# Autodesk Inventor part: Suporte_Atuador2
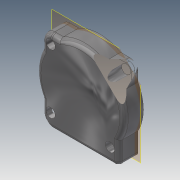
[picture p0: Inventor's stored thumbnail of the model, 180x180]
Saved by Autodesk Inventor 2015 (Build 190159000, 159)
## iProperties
Created: 2015-04
Part Number: Suporte_Atuador2
Material: Steel, Carbon
Document SubType Name: Modeling
Designer: TREINA6
Density: 7.85 g/cm^3
Appearance: Semi-Polished
Author: TREINA6
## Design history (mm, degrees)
workplane "Work Plane1"
sketch "Sketch1"
  geometry: L1 (32.5, -27.5)-(32.5, -18.708) reference; L2 (32.5, 18.708)-(32.5, 27.5) reference; L3 (27.5, 32.5)-(18.708, 32.5) reference; L4 (-18.708, 32.5)-(-27.5, 32.5) reference; L5 (-32.5, 27.5)-(-32.5, 18.708) reference; L6 (-32.5, -18.708)-(-32.5, -27.5) reference; L7 (-27.5, -32.5)-(-18.708, -32.5) reference; L8 (18.708, -32.5)-(27.5, -32.5) reference; L9 (35.5, -19.494)-(35.5, -27.5); L10 (27.5, -35.5)-(19.494, -35.5); L11 (-19.494, -35.5)-(-27.5, -35.5); L12 (-35.5, -27.5)-(-35.5, -19.494); L13 (-35.5, 19.494)-(-35.5, 27.5); L14 (-27.5, 35.5)-(-19.494, 35.5); L15 (19.494, 35.5)-(27.5, 35.5); L16 (35.5, 27.5)-(35.5, 19.494); C1 r 3.324 at (27.5, -27.5) reference; C2 r 3.324 at (-27.5, -27.5) reference; C3 r 3.324 at (-27.5, 27.5) reference; C4 r 3.324 at (27.5, 27.5) reference; C5 r 25 at (0, 0) reference; A1 r 5 centre (27.5, -27.5) between (27.5, -32.5) and (32.5, -27.5) reference; A2 r 37.5 centre (0, 0) between (32.5, -18.708) and (32.5, 18.708) reference; A3 r 5 centre (27.5, 27.5) between (32.5, 27.5) and (27.5, 32.5) reference; A4 r 37.5 centre (0, 0) between (18.708, 32.5) and (-18.708, 32.5) reference; A5 r 5 centre (-27.5, 27.5) between (-27.5, 32.5) and (-32.5, 27.5) reference; A6 r 37.5 centre (0, 0) between (-32.5, 18.708) and (-32.5, -18.708) reference; A7 r 5 centre (-27.5, -27.5) between (-32.5, -27.5) and (-27.5, -32.5) reference; A8 r 37.5 centre (0, 0) between (-18.708, -32.5) and (18.708, -32.5) reference; A9 r 40.5 centre (0, 0) between (35.5, -19.494) and (35.5, 19.494); A10 r 8 centre (27.5, -27.5) between (27.5, -35.5) and (35.5, -27.5); A11 r 40.5 centre (0, 0) between (-19.494, -35.5) and (19.494, -35.5); A12 r 8 centre (-27.5, -27.5) between (-35.5, -27.5) and (-27.5, -35.5); A13 r 40.5 centre (0, 0) between (-35.5, 19.494) and (-35.5, -19.494); A14 r 8 centre (-27.5, 27.5) between (-27.5, 35.5) and (-35.5, 27.5); A15 r 40.5 centre (0, 0) between (19.494, 35.5) and (-19.494, 35.5); A16 r 8 centre (27.5, 27.5) between (35.5, 27.5) and (27.5, 35.5); 1 further point
  constraints: 16 end point, 16 point on circle, 8 centre point, 15 other
  dimensions: "d0" = 3 radial gap between concentric circles of A2 A9
extrude "Extrusion1" new body sketch "Sketch1" distance "d1" = 15; taper "d3" = 0 deg; dims "d2" = 3, "d4" = 0
sketch "Sketch2"
  geometry: L1 (27.5, -32.5)-(18.708, -32.5) reference; L2 (-18.708, -32.5)-(-27.5, -32.5) reference; L3 (-32.5, -27.5)-(-32.5, -18.708) reference; L4 (-32.5, 18.708)-(-32.5, 27.5) reference; L5 (-27.5, 32.5)-(-18.708, 32.5) reference; L6 (18.708, 32.5)-(27.5, 32.5) reference; L7 (32.5, 27.5)-(32.5, 18.708) reference; L8 (32.5, -18.708)-(32.5, -27.5) reference; L9 (35.5, 19.494)-(35.5, 27.5) reference; L10 (27.5, 35.5)-(19.494, 35.5) reference; L11 (-19.494, 35.5)-(-27.5, 35.5) reference; L12 (-35.5, 27.5)-(-35.5, 19.494) reference; L13 (-35.5, -19.494)-(-35.5, -27.5) reference; L14 (-27.5, -35.5)-(-19.494, -35.5) reference; L15 (19.494, -35.5)-(27.5, -35.5) reference; L16 (35.5, -27.5)-(35.5, -19.494) reference; A1 r 37.5 centre (0, 0) between (-18.708, -32.5) and (18.708, -32.5) reference; A2 r 5 centre (-27.5, -27.5) between (-32.5, -27.5) and (-27.5, -32.5) reference; A3 r 37.5 centre (0, 0) between (-32.5, 18.708) and (-32.5, -18.708) reference; A4 r 5 centre (-27.5, 27.5) between (-27.5, 32.5) and (-32.5, 27.5) reference; A5 r 37.5 centre (0, 0) between (18.708, 32.5) and (-18.708, 32.5) reference; A6 r 5 centre (27.5, 27.5) between (32.5, 27.5) and (27.5, 32.5) reference; A7 r 37.5 centre (0, 0) between (32.5, -18.708) and (32.5, 18.708) reference; A8 r 5 centre (27.5, -27.5) between (27.5, -32.5) and (32.5, -27.5) reference; A9 r 40.5 centre (0, 0) between (35.5, -19.494) and (35.5, 19.494) reference; A10 r 8 centre (27.5, 27.5) between (35.5, 27.5) and (27.5, 35.5) reference; A11 r 40.5 centre (0, 0) between (19.494, 35.5) and (-19.494, 35.5) reference; A12 r 8 centre (-27.5, 27.5) between (-27.5, 35.5) and (-35.5, 27.5) reference; A13 r 40.5 centre (0, 0) between (-35.5, 19.494) and (-35.5, -19.494) reference; A14 r 8 centre (-27.5, -27.5) between (-35.5, -27.5) and (-27.5, -35.5) reference; A15 r 40.5 centre (0, 0) between (-19.494, -35.5) and (19.494, -35.5) reference; A16 r 8 centre (27.5, -27.5) between (27.5, -35.5) and (35.5, -27.5) reference; 1 further point
extrude "Extrusion2" join sketch "Sketch2" distance "d5" = 15; taper "d6" = 0 deg
hole "Hole1" diameter "d9" = 8.5; stored, may be unused: countersink angle "d13" = 82 deg, drill point angle "d15" = 118 deg; dims "d10" = 19.05, "d11" = 13, "d12" = 5, "d14" = 25.4, "d34" = 25.4, "d35" = 25.4
pattern_circular "Circular Pattern1" dims angle "d17" = 360 deg
sketch "Sketch4"
  geometry: L1 (35.5, 19.494)-(35.5, 27.5) reference; L2 (27.5, 35.5)-(19.494, 35.5) reference; L3 (-19.494, 35.5)-(-27.5, 35.5) reference; L4 (-35.5, 27.5)-(-35.5, 19.494) reference; L5 (-35.5, -19.494)-(-35.5, -27.5) reference; L6 (-27.5, -35.5)-(-19.494, -35.5) reference; L7 (19.494, -35.5)-(27.5, -35.5) reference; L8 (35.5, -27.5)-(35.5, -19.494) reference; L9 (35.5, -27.5)-(35.5, -40.5); L10 (35.5, -40.5)-(0, -40.5); L11 (0, -40.5)-(-35.5, -40.5); L12 (-35.5, -40.5)-(-35.5, -27.5); C1 r 4.25 at (27.5, 27.5) reference; C2 r 4.25 at (27.5, -27.5) reference; C3 r 4.25 at (-27.5, -27.5) reference; C4 r 4.25 at (-27.5, 27.5) reference; A1 r 40.5 centre (0, 0) between (35.5, -19.494) and (35.5, 19.494) reference; A2 r 8 centre (27.5, 27.5) between (35.5, 27.5) and (27.5, 35.5) reference; A3 r 40.5 centre (0, 0) between (19.494, 35.5) and (-19.494, 35.5) reference; A4 r 8 centre (-27.5, 27.5) between (-27.5, 35.5) and (-35.5, 27.5) reference; A5 r 40.5 centre (0, 0) between (-35.5, 19.494) and (-35.5, -19.494) reference; A6 r 8 centre (-27.5, -27.5) between (-35.5, -27.5) and (-27.5, -35.5) reference; A7 r 40.5 centre (0, 0) between (-19.494, -35.5) and (19.494, -35.5) reference; A8 r 8 centre (27.5, -27.5) between (27.5, -35.5) and (35.5, -27.5) reference; A9 r 8 centre (27.5, -27.5) between (27.5, -35.5) and (35.5, -27.5) reference; A10 r 40.5 centre (0, 0) between (-19.494, -35.5) and (19.494, -35.5) reference; 1 further point
  constraints: 8 end point, 2 point on circle, 2 tangent, 1 perpendicular, 1 point on line, 1 vertical
extrude "Extrusion4" join sketch "Sketch4" stored distance "d36" = 25.4; taper "d37" = 0 deg
fillet "Fillet1" dims "d33" = 4
sketch "Sketch5"
  geometry: L1 (50.208, -11)-(12.792, -11) reference; 3 further points
  constraints: 1 midpoint, 1 vertical alignment
  dimensions: "d38" = 6.5 distance from line of L1 point (31.5, -4.5)
hole "Hole3" sketch "Sketch5" at (31.5, -4.5) diameter "d39" = 10.1092; stored, may be unused: countersink angle "d43" = 82 deg, drill point angle "d45" = 118 deg; dims "d40" = 24.003, "d41" = 9.525, "d42" = 6.35, "d44" = 32.3088
chamfer "Chamfer1" distance "d46" = 1; stored, may be unused: second distance "d47" = 3.175, angle "d48" = 45 deg
body "Solid1"
node "Reference1"
node "Projected Loop1"
node "Projected Loop2"
